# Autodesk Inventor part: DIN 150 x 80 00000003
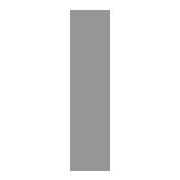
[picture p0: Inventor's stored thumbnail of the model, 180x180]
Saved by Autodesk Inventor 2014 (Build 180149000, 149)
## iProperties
_CCFamilyMember: 150
_CCFamilyDisplayName: DIN EN 10058 - Hot rolled flat steel bars for general purposes
_FrameMemberDoc: Frame Member File
_Version: 15.0.0
Created: 2009-11
Part Number: DIN 150 x 80 00000003
Material: Steel, Mild
Description: Hot rolled flat steel bars for general purposes
Document SubType Name: Modeling
Standard: DIN
Designer: pokornp
Standard Revision: 2004
Standards Organization: DIN
Language: en-US
Size Designation: 150 x 80
Categories: <MemberInstance><Categories><Category DisplayName="Structural Shapes" InternalName="089c4875-fa83-4c05-b084-43b9cc11f5ed" Mnemonic="GRDR"><CategoryParameter Dis
Stock Number: 150 x 80
Density: 7.86 g/cm^3
Appearance: Steel
IsCustomPart: 1
G_L: 900.000 mm
G_W: 80.000 mm
G_H: 150.000 mm
Author: pokornp
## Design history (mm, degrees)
node "Start plane"
node "End plane"
sketch "Sketch"
  geometry: L1 (40, -75)-(-40, -75); L2 (-40, -75)-(-40, 75); L3 (-40, 75)-(40, 75); L4 (40, 75)-(40, -75); L5 (-6, 0)-(8, 0); L6 (0, -30)-(0, 40); L7 (0, 105)-(0, -105) reference; L8 (-56, 0)-(56, 0) reference
  constraints: 12 end point, 2 collinear, 2 parallel, 1 horizontal, 1 perpendicular
  dimensions: "d0" = 150 distance between parallel lines of L3 L1 (= G_W); "d1" = 80 distance between parallel lines of L4 L2 (= G_H); "d4" = 40 distance between parallel lines of L6 L4 (= 0.5 x d1); "d5" = 75 distance between parallel lines of L5 L3 (= 0.5 x d0)
extrude "Body" new body sketch "Sketch" stored distance "d2" = 900 (= G_L); taper "d3" = 0 deg
node "Driven Length"
  sketch "Sketch3"
    geometry: L1 (0, 0)-(10, 0) reference
    constraints: 2 end point, 1 horizontal
  workplane "Work Plane3"
  sketch "Sketch4"
    geometry: L1 (-2, 0)-(12, 0) reference; L2 (-2, 900)-(12, 900) reference
    dimensions: "d9" = 900 distance between parallel lines of L1 L2 (derived)
body "Solid1"
other parameters: "G_W" = 150 [user parameter; used in 1 equation term], "G_H" = 80 [user parameter; used in 1 equation term], "G_L" = 900 (= d9) [user parameter; used in 1 equation term], "G_OFFSET_START" = 0 [user parameter; used in 1 equation term], "G_OFFSET_END" = 0 [user parameter; used in 1 equation term], "d6" = 0 (computed from G_OFFSET_START), "d8" = 90 deg, "MAS" = 9.42 [user parameter]
